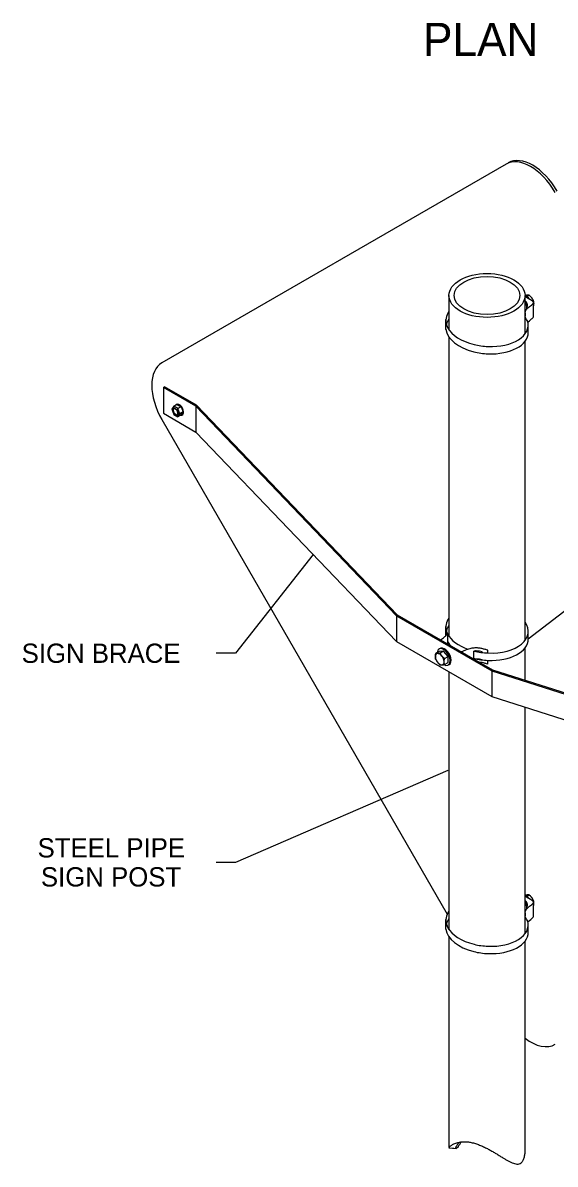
# Model space of a CAD drawing. Extents: x 99988 to 100172, y 99995 to 100047.
# Drawn here: x 100010.851 to 100012.785, y 100001.552 to 100005.697 of the extents above; entities that cross this region are included whole.
import ezdxf

# ---------------------------------------------------------------- set-up
doc = ezdxf.new("R2010")
doc.units = 0
for name, color, linetype in [('Level 15', 7, 'Continuous'), ('Level 20', 7, 'Continuous'), ('Level 3', 7, 'Continuous')]:
    doc.layers.add(name, color=color, linetype=linetype)

msp = doc.modelspace()

# ---------------------------------------------------------------- linework, layer by layer
at = {"layer": 'Level 15'}
for points in [[(100012.6866, 100003.4594), (100013.5991, 100004.1594), (100013.6691, 100004.1594)], [(100011.9054, 100003.7655), (100011.6228, 100003.4072), (100011.5528, 100003.4072)], [(100012.395, 100002.9811), (100011.6228, 100002.6478), (100011.5528, 100002.6478)]]:
    msp.add_lwpolyline(points, dxfattribs=at)
at = {"layer": 'Level 3'}
for p, q in [((100012.6061, 100005.1836), (100011.3559, 100004.4618)), ((100012.3989, 100004.7064), (100012.3989, 100004.5819)), ((100012.675, 100004.7064), (100012.675, 100004.5667)), ((100012.6821, 100004.7026), (100012.6901, 100004.7072)), ((100012.675, 100004.6796), (100012.6806, 100004.6727)), ((100012.675, 100004.6695), (100012.6806, 100004.6727)), ((100012.6806, 100004.6727), (100012.6806, 100004.6559)), ((100012.6996, 100004.6979), (100012.6993, 100004.6984)), ((100012.7023, 100004.6853), (100012.706, 100004.6874)), ((100012.7056, 100004.6294), (100012.7056, 100004.6801)), ((100012.7056, 100004.666), (100012.706, 100004.6662)), ((100012.7074, 100004.6781), (100012.7074, 100004.6772)), ((100012.6757, 100004.6428), (100012.6757, 100004.6317)), ((100012.3877, 100004.5834), (100012.3874, 100004.6186)), ((100012.3874, 100004.6143), (100012.3874, 100004.6156)), ((100012.6866, 100004.5725), (100012.6866, 100004.5992)), ((100012.3989, 100004.5552), (100012.3989, 100004.5516)), ((100012.3989, 100004.5552), (100012.3989, 100003.4687)), ((100012.675, 100004.54), (100012.675, 100003.4535)), ((100011.3559, 100004.4617), (100011.3559, 100004.4617)), ((100011.3611, 100004.3722), (100011.3657, 100004.3748)), ((100011.3611, 100004.3722), (100011.3611, 100004.2785)), ((100011.479, 100004.3041), (100011.3611, 100004.3722)), ((100011.4819, 100004.3077), (100011.3657, 100004.3748)), ((100011.3991, 100004.3039), (100011.3918, 100004.2935)), ((100011.3918, 100004.2935), (100011.3991, 100004.2746)), ((100011.3958, 100004.2902), (100011.3918, 100004.2935)), ((100011.3958, 100004.2902), (100011.3983, 100004.2937)), ((100011.3983, 100004.2839), (100011.3958, 100004.2902)), ((100011.3983, 100004.2937), (100011.4007, 100004.2971)), ((100011.411, 100004.3108), (100011.3991, 100004.3039)), ((100011.4007, 100004.2971), (100011.3991, 100004.3039)), ((100011.4138, 100004.2955), (100011.3991, 100004.3039)), ((100011.4007, 100004.2971), (100011.4056, 100004.2943)), ((100011.4056, 100004.2943), (100011.4105, 100004.2915)), ((100011.4082, 100004.3107), (100011.4082, 100004.3107)), ((100011.4138, 100004.2955), (100011.4105, 100004.2915)), ((100011.4105, 100004.2915), (100011.413, 100004.2852)), ((100011.411, 100004.3108), (100011.4257, 100004.3023)), ((100011.4257, 100004.3023), (100011.4138, 100004.2955)), ((100011.4211, 100004.2765), (100011.4138, 100004.2955)), ((100011.4257, 100004.3023), (100011.433, 100004.2834)), ((100011.479, 100004.3041), (100012.2081, 100003.5434)), ((100011.479, 100004.3041), (100011.479, 100004.2104)), ((100011.4819, 100004.3077), (100012.2109, 100003.547)), ((100011.3559, 100004.2555), (100012.3926, 100002.4599)), ((100011.3611, 100004.2785), (100011.479, 100004.2104)), ((100011.4007, 100004.2775), (100011.3983, 100004.2839)), ((100011.4007, 100004.2775), (100011.3991, 100004.2746)), ((100011.3991, 100004.2746), (100011.4138, 100004.2661)), ((100011.4056, 100004.2747), (100011.4007, 100004.2775)), ((100011.4105, 100004.2719), (100011.4056, 100004.2747)), ((100011.413, 100004.2754), (100011.4105, 100004.2719)), ((100011.4105, 100004.2719), (100011.4138, 100004.2661)), ((100011.4116, 100004.2741), (100011.4124, 100004.2746)), ((100011.413, 100004.2852), (100011.4154, 100004.2789)), ((100011.4154, 100004.2789), (100011.413, 100004.2754)), ((100011.4138, 100004.2661), (100011.4211, 100004.2765)), ((100011.4257, 100004.2729), (100011.4138, 100004.2661)), ((100011.4154, 100004.2789), (100011.4211, 100004.2765)), ((100011.433, 100004.2834), (100011.4211, 100004.2765)), ((100011.433, 100004.2834), (100011.4257, 100004.2729)), ((100011.479, 100004.2104), (100012.2081, 100003.4497)), ((100012.2081, 100003.5434), (100012.5547, 100003.3433)), ((100012.2081, 100003.5434), (100012.2081, 100003.4497)), ((100012.2109, 100003.547), (100012.5565, 100003.3474)), ((100012.3874, 100003.5011), (100012.3874, 100003.5025)), ((100012.6866, 100003.4594), (100012.6866, 100003.4861)), ((100012.2081, 100003.4497), (100012.5547, 100003.2496)), ((100012.3989, 100003.442), (100012.3989, 100003.4384)), ((100012.675, 100003.4269), (100012.675, 100003.309)), ((100012.3636, 100003.4133), (100012.3509, 100003.406)), ((100012.3795, 100003.4148), (100012.3636, 100003.4133)), ((100012.3795, 100003.4148), (100012.3668, 100003.4074)), ((100012.3735, 100003.3965), (100012.3732, 100003.3969)), ((100012.3795, 100003.4148), (100012.3795, 100003.4148)), ((100012.3954, 100003.395), (100012.3795, 100003.4148)), ((100012.3827, 100003.3876), (100012.3954, 100003.395)), ((100012.3954, 100003.3738), (100012.3954, 100003.395)), ((100012.5404, 100003.4081), (100012.5404, 100003.418)), ((100012.5404, 100003.3673), (100012.5404, 100003.3814)), ((100012.3572, 100003.3744), (100012.3577, 100003.3737)), ((100012.373, 100003.3648), (100012.3737, 100003.3649)), ((100012.3813, 100003.3757), (100012.3813, 100003.3766)), ((100012.3827, 100003.3664), (100012.3954, 100003.3738)), ((100012.3998, 100003.3667), (100012.3963, 100003.3646)), ((100012.3989, 100003.3395), (100012.3989, 100002.4038)), ((100012.5547, 100003.3433), (100012.5547, 100003.2496)), ((100012.5547, 100003.3433), (100013.8705, 100002.9234)), ((100012.5565, 100003.3474), (100013.8729, 100002.9274)), ((100012.675, 100003.2112), (100012.675, 100002.3887)), ((100012.6821, 100002.5246), (100012.6901, 100002.5292)), ((100012.6996, 100002.5199), (100012.6993, 100002.5203)), ((100012.7023, 100002.5072), (100012.706, 100002.5094)), ((100012.675, 100002.5015), (100012.6806, 100002.4947)), ((100012.675, 100002.4915), (100012.6806, 100002.4947)), ((100012.6806, 100002.4947), (100012.6806, 100002.4778)), ((100012.7056, 100002.4514), (100012.7056, 100002.5021)), ((100012.7056, 100002.488), (100012.706, 100002.4882)), ((100012.7074, 100002.5), (100012.7074, 100002.5)), ((100012.7074, 100002.5), (100012.7074, 100002.4991)), ((100012.3877, 100002.4054), (100012.3874, 100002.4406)), ((100012.3874, 100002.4362), (100012.3874, 100002.4376)), ((100012.6757, 100002.4648), (100012.6757, 100002.4536)), ((100012.6866, 100002.3945), (100012.6866, 100002.4212)), ((100012.3989, 100002.3771), (100012.3989, 100002.3735)), ((100012.3989, 100002.3771), (100012.3989, 100001.6118)), ((100012.675, 100002.362), (100012.675, 100001.6109)), ((100012.424, 100001.6109), (100012.424, 100001.6109))]:
    msp.add_line(p, q, dxfattribs=at)
for points in [[(100012.3869, 100003.4703), (100012.3869, 100003.4899), (100012.3869, 100003.5046)], [(100012.3941, 100003.4412), (100012.3941, 100003.474), (100012.3941, 100003.4746)], [(100012.4892, 100003.3863), (100012.4892, 100003.4143), (100012.4892, 100003.415)], [(100012.5196, 100003.4098), (100012.5196, 100003.4118), (100012.5196, 100003.4124)], [(100012.5547, 100003.2496), (100013.8705, 100002.8297), (100013.9883, 100002.7617), (100013.993, 100002.7644)], [(100012.3989, 100001.6106), (100012.4011, 100001.6106), (100012.4121, 100001.61), (100012.4166, 100001.6096), (100012.4251, 100001.6089)]]:
    msp.add_lwpolyline(points, dxfattribs=at)
for centre, major_axis, ratio, start_param, end_param in [((100012.6954, 100005.0288), (-0.0893, 0.1547), 0.57735, 4.712501, 6.283245), ((100012.703, 100005.0333), (-0.0893, 0.1547), 0.57735, 4.712501, 6.283245), ((100012.6775, 100004.6786), (-0.0167, 0.0289), 0.57735, 4.88098, 5.600538), ((100012.6915, 100004.6868), (0.0113, -0.0195), 0.57735, 2.774706, 2.95901), ((100012.6739, 100004.6766), (-0.0167, 0.0289), 0.57735, 5.273285, 5.45034), ((100012.6915, 100004.6868), (0.0113, -0.0195), 0.57735, 1.84578, 1.845825), ((100012.537, 100004.6074), (-0.1495, 0.0122), 0.572172, 5.934267, 6.519612), ((100012.537, 100004.5808), (-0.1495, 0.0122), 0.572172, 5.934267, 6.168149), ((100012.537, 100004.5808), (-0.1495, 0.0122), 0.572172, 0.110717, 1.292596), ((100012.537, 100004.6074), (-0.1495, 0.0122), 0.572172, 0.236427, 0.313637), ((100012.537, 100004.6074), (-0.1495, 0.0122), 0.572172, 0.236427, 0.442391), ((100012.537, 100004.6074), (-0.1495, 0.0122), 0.572172, 0.347979, 1.301076), ((100012.537, 100004.6074), (-0.1495, 0.0122), 0.572172, 1.640716, 3.340319), ((100012.537, 100004.5808), (-0.1495, 0.0122), 0.572172, 1.640716, 3.188329), ((100012.537, 100004.5808), (-0.1495, 0.0122), 0.572172, 1.292596, 1.640716), ((100012.537, 100004.6074), (-0.1495, 0.0122), 0.572172, 1.301076, 1.640716), ((100011.4452, 100004.307), (0.0893, -0.1547), 0.57735, 3.141599, 4.712454), ((100011.4056, 100004.2845), (-0.006, 0.0104), 0.57735, 0.261799, 1.308997), ((100011.4056, 100004.2845), (-0.006, 0.0104), 0.57735, 5.497787, 6.544985), ((100011.4192, 100004.2918), (-0.0109, 0.019), 0.57735, 2.677051, 6.629325), ((100011.4056, 100004.2845), (-0.006, 0.0104), 0.57735, 4.45059, 5.497787), ((100011.4056, 100004.2845), (-0.006, 0.0104), 0.57735, 1.308997, 2.356194), ((100011.4056, 100004.2845), (-0.006, 0.0104), 0.57735, 2.356194, 3.403392), ((100011.4056, 100004.2845), (-0.006, 0.0104), 0.57735, 3.403392, 4.45059), ((100012.537, 100003.4943), (-0.1495, 0.0122), 0.572172, 5.934267, 6.519612), ((100012.537, 100003.4676), (-0.1495, 0.0122), 0.572172, 5.934267, 6.168149), ((100012.537, 100003.4943), (-0.1495, 0.0122), 0.572172, 1.640716, 3.583984), ((100012.537, 100003.4943), (-0.1495, 0.0122), 0.572172, 0.236427, 0.313637), ((100012.537, 100003.4943), (-0.1495, 0.0122), 0.572172, 0.236427, 0.442391), ((100012.537, 100003.4943), (-0.1495, 0.0122), 0.572172, 0.347979, 1.136905), ((100012.3796, 100003.3935), (-0.0167, 0.0289), 0.57735, 6.176919, 6.997221), ((100012.3832, 100003.3955), (-0.0167, 0.0289), 0.57735, 3.141593, 6.389451), ((100012.3796, 100003.3935), (-0.0167, 0.0289), 0.57735, 2.383055, 6.176919), ((100012.537, 100003.4676), (-0.1495, 0.0122), 0.572172, 0.347812, 0.522242), ((100012.537, 100003.4676), (-0.1495, 0.0122), 0.572172, 1.640716, 3.188329), ((100012.3654, 100003.3854), (0.0113, -0.0195), 0.57735, 1.84578, 3.926991), ((100012.3654, 100003.3854), (0.0113, -0.0195), 0.57735, 3.926991, 4.953299), ((100012.3654, 100003.3854), (0.0113, -0.0195), 0.57735, 0.810125, 1.819366), ((100012.537, 100003.4676), (-0.1495, 0.0122), 0.572172, 1.292596, 1.640716), ((100012.537, 100003.4943), (-0.1495, 0.0122), 0.572172, 1.301076, 1.640716), ((100012.3654, 100003.3854), (0.0113, -0.0195), 0.57735, 4.995078, 5.994144), ((100012.3654, 100003.3854), (0.0113, -0.0195), 0.57735, 6.048628, 7.043856), ((100012.6775, 100002.5006), (-0.0167, 0.0289), 0.57735, 4.88098, 5.600538), ((100012.6739, 100002.4985), (-0.0167, 0.0289), 0.57735, 5.273285, 5.45034), ((100012.6915, 100002.5088), (0.0113, -0.0195), 0.57735, 2.774706, 2.95901), ((100012.6915, 100002.5088), (0.0113, -0.0195), 0.57735, 1.84578, 1.845825), ((100012.537, 100002.4294), (-0.1495, 0.0122), 0.572172, 5.934267, 6.519612), ((100012.537, 100002.4027), (-0.1495, 0.0122), 0.572172, 5.934267, 6.168149), ((100012.537, 100002.4294), (-0.1495, 0.0122), 0.572172, 1.640716, 3.340319), ((100012.537, 100002.4027), (-0.1495, 0.0122), 0.572172, 0.110717, 1.292596), ((100012.537, 100002.4294), (-0.1495, 0.0122), 0.572172, 0.236427, 0.313637), ((100012.537, 100002.4294), (-0.1495, 0.0122), 0.572172, 0.236427, 0.442391), ((100012.537, 100002.4294), (-0.1495, 0.0122), 0.572172, 0.347979, 1.301076), ((100012.537, 100002.4027), (-0.1495, 0.0122), 0.572172, 1.640716, 3.188329), ((100012.537, 100002.4294), (-0.1495, 0.0122), 0.572172, 1.301076, 1.640716), ((100012.537, 100002.4027), (-0.1495, 0.0122), 0.572172, 1.292596, 1.640716), ((100012.6954, 100002.1417), (0.0893, -0.1547), 0.57735, 5.336076, 6.283182)]:
    msp.add_ellipse(centre, major_axis=major_axis, ratio=ratio, start_param=start_param, end_param=end_param, dxfattribs=at)
for major_axis in [(0.1381, 0), (0.1197, 0)]:
    msp.add_ellipse((100012.537, 100004.7064), major_axis=major_axis, ratio=0.57735, dxfattribs=at)
for points, degree in [([(100012.6901, 100004.7072), (100012.687, 100004.7077), (100012.6824, 100004.7074), (100012.6766, 100004.7063)], 2), ([(100012.6993, 100004.6984), (100012.6991, 100004.6985), (100012.699, 100004.6987), (100012.6989, 100004.6988), (100012.6963, 100004.7019), (100012.6933, 100004.7047), (100012.6901, 100004.7072)], 3), ([(100012.6757, 100004.6419), (100012.6756, 100004.6431), (100012.6759, 100004.6457), (100012.6781, 100004.6536), (100012.6871, 100004.6636), (100012.7037, 100004.6748), (100012.7072, 100004.6807), (100012.7029, 100004.6864), (100012.6755, 100004.7022), (100012.6753, 100004.7023), (100012.6752, 100004.7024), (100012.675, 100004.7025)], 3), ([(100012.6806, 100004.6632), (100012.6811, 100004.6634), (100012.6815, 100004.6637), (100012.6819, 100004.6641), (100012.6826, 100004.6647), (100012.6832, 100004.6657), (100012.6836, 100004.6667), (100012.6839, 100004.6678), (100012.6841, 100004.6691), (100012.6841, 100004.6705), (100012.6841, 100004.6719), (100012.6838, 100004.6734), (100012.6834, 100004.6749), (100012.683, 100004.6765), (100012.6824, 100004.678), (100012.6817, 100004.6795), (100012.6809, 100004.681), (100012.68, 100004.6825), (100012.679, 100004.6838), (100012.6779, 100004.6851), (100012.6768, 100004.6862), (100012.6756, 100004.6872), (100012.6754, 100004.6874), (100012.6752, 100004.6875), (100012.675, 100004.6877)], 3), ([(100012.706, 100004.6874), (100012.7043, 100004.691), (100012.7022, 100004.6946), (100012.6996, 100004.6979)], 2), ([(100012.7056, 100004.6663), (100012.7057, 100004.6662), (100012.7059, 100004.6662), (100012.706, 100004.6662)], 2), ([(100012.7074, 100004.6781), (100012.7074, 100004.6815), (100012.7068, 100004.6846), (100012.706, 100004.6874)], 2), ([(100012.706, 100004.6662), (100012.7068, 100004.67), (100012.7074, 100004.6737), (100012.7074, 100004.6772)], 2), ([(100012.6849, 100004.6123), (100012.6779, 100004.6231), (100012.6754, 100004.63), (100012.6756, 100004.6322), (100012.6757, 100004.6329)], 3), ([(100012.685, 100004.6094), (100012.6945, 100004.6179), (100012.7031, 100004.6239), (100012.7056, 100004.6275), (100012.7056, 100004.6294)], 3), ([(100012.369, 100003.4557), (100012.3724, 100003.4584), (100012.3828, 100003.4656), (100012.3902, 100003.4736), (100012.3922, 100003.4783), (100012.3927, 100003.4797)], 3), ([(100012.3941, 100003.4746), (100012.3941, 100003.4754), (100012.3941, 100003.4761), (100012.3939, 100003.477)], 2), ([(100012.3941, 100003.4453), (100012.3941, 100003.4456), (100012.3941, 100003.4458), (100012.3941, 100003.4461)], 2), ([(100012.5404, 100003.418), (100012.5363, 100003.4191), (100012.5322, 100003.4203), (100012.528, 100003.4214), (100012.5156, 100003.4249), (100012.5006, 100003.4268), (100012.4942, 100003.4266), (100012.4784, 100003.4252), (100012.4616, 100003.4201), (100012.4492, 100003.4141), (100012.4445, 100003.4121)], 3), ([(100012.3495, 100003.3946), (100012.3495, 100003.3981), (100012.35, 100003.4021), (100012.3509, 100003.406)], 2), ([(100012.3509, 100003.406), (100012.3503, 100003.403), (100012.3498, 100003.4001), (100012.3496, 100003.3973), (100012.3495, 100003.3964), (100012.3495, 100003.3955), (100012.3495, 100003.3946)], 3), ([(100012.3509, 100003.406), (100012.35, 100003.4021), (100012.3495, 100003.3981), (100012.3495, 100003.3946)], 2), ([(100012.3509, 100003.3848), (100012.35, 100003.3877), (100012.3495, 100003.391), (100012.3495, 100003.3946)], 2), ([(100012.3668, 100003.4074), (100012.3599, 100003.4059), (100012.3544, 100003.4055), (100012.3509, 100003.406)], 2), ([(100012.3668, 100003.4074), (100012.3631, 100003.4066), (100012.3597, 100003.406), (100012.3569, 100003.4058), (100012.3545, 100003.4056), (100012.3525, 100003.4057), (100012.3509, 100003.406)], 3), ([(100012.3509, 100003.3848), (100012.3526, 100003.3812), (100012.3546, 100003.3777), (100012.3572, 100003.3744)], 2), ([(100012.3509, 100003.3848), (100012.3526, 100003.3812), (100012.3546, 100003.3777), (100012.3572, 100003.3744)], 2), ([(100012.3732, 100003.3969), (100012.373, 100003.3971), (100012.3729, 100003.3972), (100012.3728, 100003.3974), (100012.3704, 100003.4005), (100012.3684, 100003.404), (100012.3668, 100003.4074)], 3), ([(100012.3732, 100003.3969), (100012.3705, 100003.4002), (100012.3685, 100003.4038), (100012.3668, 100003.4074)], 2), ([(100012.3827, 100003.3876), (100012.3794, 100003.3903), (100012.3762, 100003.3932), (100012.3735, 100003.3965)], 2), ([(100012.3827, 100003.3876), (100012.3793, 100003.3903), (100012.3762, 100003.3932), (100012.3735, 100003.3965)], 2), ([(100012.3813, 100003.3766), (100012.3813, 100003.3774), (100012.3813, 100003.3782), (100012.3814, 100003.379), (100012.3816, 100003.3817), (100012.3821, 100003.3847), (100012.3827, 100003.3876)], 3), ([(100012.3813, 100003.3766), (100012.3813, 100003.3801), (100012.3819, 100003.3839), (100012.3827, 100003.3876)], 2), ([(100012.3813, 100003.3766), (100012.3813, 100003.3801), (100012.3819, 100003.3838), (100012.3827, 100003.3876)], 2), ([(100012.5196, 100003.4124), (100012.512, 100003.4142), (100012.5, 100003.4156), (100012.4958, 100003.4155), (100012.4905, 100003.4151), (100012.4892, 100003.415)], 3), ([(100012.5196, 100003.3831), (100012.512, 100003.3849), (100012.5, 100003.3863), (100012.4959, 100003.3862), (100012.491, 100003.3859), (100012.4901, 100003.3858)], 3), ([(100012.3577, 100003.3737), (100012.3604, 100003.3705), (100012.3635, 100003.3676), (100012.3668, 100003.365)], 2), ([(100012.3668, 100003.365), (100012.3685, 100003.3647), (100012.3704, 100003.3646), (100012.373, 100003.3648)], 2), ([(100012.3668, 100003.365), (100012.3684, 100003.3647), (100012.3705, 100003.3646), (100012.373, 100003.3648)], 2), ([(100012.3737, 100003.3649), (100012.3763, 100003.3652), (100012.3794, 100003.3657), (100012.3827, 100003.3664)], 2), ([(100012.3737, 100003.3649), (100012.3738, 100003.3649), (100012.3738, 100003.3649), (100012.3739, 100003.3649), (100012.3765, 100003.3652), (100012.3795, 100003.3657), (100012.3827, 100003.3664)], 3), ([(100012.3827, 100003.3664), (100012.3825, 100003.3671), (100012.3823, 100003.3678), (100012.3822, 100003.3686), (100012.3816, 100003.3708), (100012.3813, 100003.3732), (100012.3813, 100003.3757)], 3), ([(100012.3827, 100003.3664), (100012.3819, 100003.3692), (100012.3813, 100003.3723), (100012.3813, 100003.3757)], 2), ([(100012.3827, 100003.3664), (100012.3819, 100003.3692), (100012.3813, 100003.3723), (100012.3813, 100003.3757)], 2), ([(100012.5404, 100003.3673), (100012.5363, 100003.3684), (100012.5322, 100003.3696), (100012.528, 100003.3707), (100012.5197, 100003.3731), (100012.5135, 100003.3743), (100012.5089, 100003.3749)], 3), ([(100012.6757, 100002.4639), (100012.6756, 100002.4651), (100012.6759, 100002.4676), (100012.6781, 100002.4756), (100012.6871, 100002.4855), (100012.7037, 100002.4967), (100012.7072, 100002.5026), (100012.7029, 100002.5083), (100012.6755, 100002.5242), (100012.6753, 100002.5242), (100012.6752, 100002.5243), (100012.675, 100002.5244)], 3), ([(100012.6806, 100002.4851), (100012.6811, 100002.4854), (100012.6815, 100002.4857), (100012.6819, 100002.486), (100012.6826, 100002.4867), (100012.6832, 100002.4876), (100012.6836, 100002.4887), (100012.6839, 100002.4898), (100012.6841, 100002.4911), (100012.6841, 100002.4925), (100012.6841, 100002.4938), (100012.6838, 100002.4954), (100012.6834, 100002.4969), (100012.683, 100002.4984), (100012.6824, 100002.5), (100012.6817, 100002.5015), (100012.6809, 100002.503), (100012.68, 100002.5044), (100012.679, 100002.5057), (100012.6779, 100002.507), (100012.6768, 100002.5082), (100012.6756, 100002.5091), (100012.6754, 100002.5093), (100012.6752, 100002.5095), (100012.675, 100002.5096)], 3), ([(100012.6901, 100002.5292), (100012.687, 100002.5296), (100012.6824, 100002.5293), (100012.6766, 100002.5282)], 2), ([(100012.6901, 100002.5292), (100012.6882, 100002.5294), (100012.6859, 100002.5295), (100012.683, 100002.5292), (100012.6811, 100002.529), (100012.6789, 100002.5287), (100012.6766, 100002.5282)], 3), ([(100012.6993, 100002.5203), (100012.6991, 100002.5205), (100012.699, 100002.5206), (100012.6989, 100002.5208), (100012.6963, 100002.5238), (100012.6933, 100002.5266), (100012.6901, 100002.5292)], 3), ([(100012.6993, 100002.5203), (100012.6966, 100002.5236), (100012.6935, 100002.5265), (100012.6901, 100002.5292)], 2), ([(100012.706, 100002.5094), (100012.7043, 100002.513), (100012.7023, 100002.5166), (100012.6996, 100002.5199)], 2), ([(100012.706, 100002.5094), (100012.7043, 100002.513), (100012.7022, 100002.5166), (100012.6996, 100002.5199)], 2), ([(100012.7074, 100002.5), (100012.7074, 100002.5008), (100012.7074, 100002.5015), (100012.7073, 100002.5023), (100012.7071, 100002.5048), (100012.7066, 100002.5072), (100012.706, 100002.5094)], 3), ([(100012.7074, 100002.5), (100012.7074, 100002.5035), (100012.7068, 100002.5066), (100012.706, 100002.5094)], 2), ([(100012.7074, 100002.5), (100012.7074, 100002.5034), (100012.7068, 100002.5066), (100012.706, 100002.5094)], 2), ([(100012.7056, 100002.4882), (100012.7057, 100002.4882), (100012.7059, 100002.4882), (100012.706, 100002.4882)], 2), ([(100012.706, 100002.4882), (100012.7062, 100002.4891), (100012.7064, 100002.49), (100012.7065, 100002.491), (100012.7071, 100002.4938), (100012.7074, 100002.4965), (100012.7074, 100002.4991)], 3), ([(100012.706, 100002.4882), (100012.7068, 100002.4919), (100012.7074, 100002.4957), (100012.7074, 100002.4991)], 2), ([(100012.706, 100002.4882), (100012.7068, 100002.492), (100012.7074, 100002.4957), (100012.7074, 100002.4991)], 2), ([(100012.6849, 100002.4343), (100012.6779, 100002.4451), (100012.6754, 100002.452), (100012.6756, 100002.4541), (100012.6757, 100002.4549)], 3), ([(100012.685, 100002.4313), (100012.6945, 100002.4398), (100012.7031, 100002.4459), (100012.7056, 100002.4494), (100012.7056, 100002.4514)], 3), ([(100012.3989, 100001.6106), (100012.3987, 100001.6106), (100012.3986, 100001.6111), (100012.3993, 100001.6125), (100012.4009, 100001.6147), (100012.4036, 100001.6172), (100012.4072, 100001.6199), (100012.4116, 100001.6228), (100012.4168, 100001.6257), (100012.4233, 100001.6284), (100012.4309, 100001.6308), (100012.4399, 100001.6326), (100012.4504, 100001.6337), (100012.4625, 100001.6333), (100012.4762, 100001.6315), (100012.491, 100001.6281), (100012.5062, 100001.623), (100012.521, 100001.6167), (100012.5351, 100001.61), (100012.5483, 100001.6028), (100012.5607, 100001.5957), (100012.5725, 100001.5887), (100012.5837, 100001.5818), (100012.5943, 100001.5753), (100012.6044, 100001.5692), (100012.6142, 100001.5636), (100012.6236, 100001.5589), (100012.6328, 100001.5549), (100012.6414, 100001.5522), (100012.6498, 100001.5515), (100012.6577, 100001.5531), (100012.6622, 100001.5573), (100012.6644, 100001.56)], 3), ([(100012.4325, 100001.6154), (100012.4309, 100001.6133), (100012.428, 100001.6098), (100012.4253, 100001.6087), (100012.424, 100001.6093), (100012.4238, 100001.6113), (100012.4244, 100001.614), (100012.4258, 100001.6174), (100012.428, 100001.6212), (100012.4309, 100001.6252), (100012.4341, 100001.6288), (100012.4367, 100001.6311), (100012.4379, 100001.632)], 3), ([(100012.4325, 100001.6154), (100012.4343, 100001.6181), (100012.4376, 100001.6234), (100012.4414, 100001.6299), (100012.4432, 100001.6328)], 3), ([(100012.675, 100001.6109), (100012.675, 100001.6069), (100012.6747, 100001.5977), (100012.6732, 100001.584), (100012.67, 100001.5703), (100012.6665, 100001.5632), (100012.6644, 100001.56)], 3)]:
    msp.add_open_spline(points, degree=degree, dxfattribs=at)

# ---------------------------------------------------------------- texts
at = {"layer": 'Level 20'}
for s, height, p in [('PLAN', 0.12, (100012.3046, 100005.5765)), ('SIGN BRACE', 0.07, (100010.8463, 100003.3722)), ('STEEL PIPE', 0.07, (100010.9042, 100002.6656)), ('SIGN POST', 0.07, (100010.9163, 100002.5601))]:
    msp.add_text(s, height=height, dxfattribs=at).set_placement(p)

doc.saveas('drawing.dxf')
